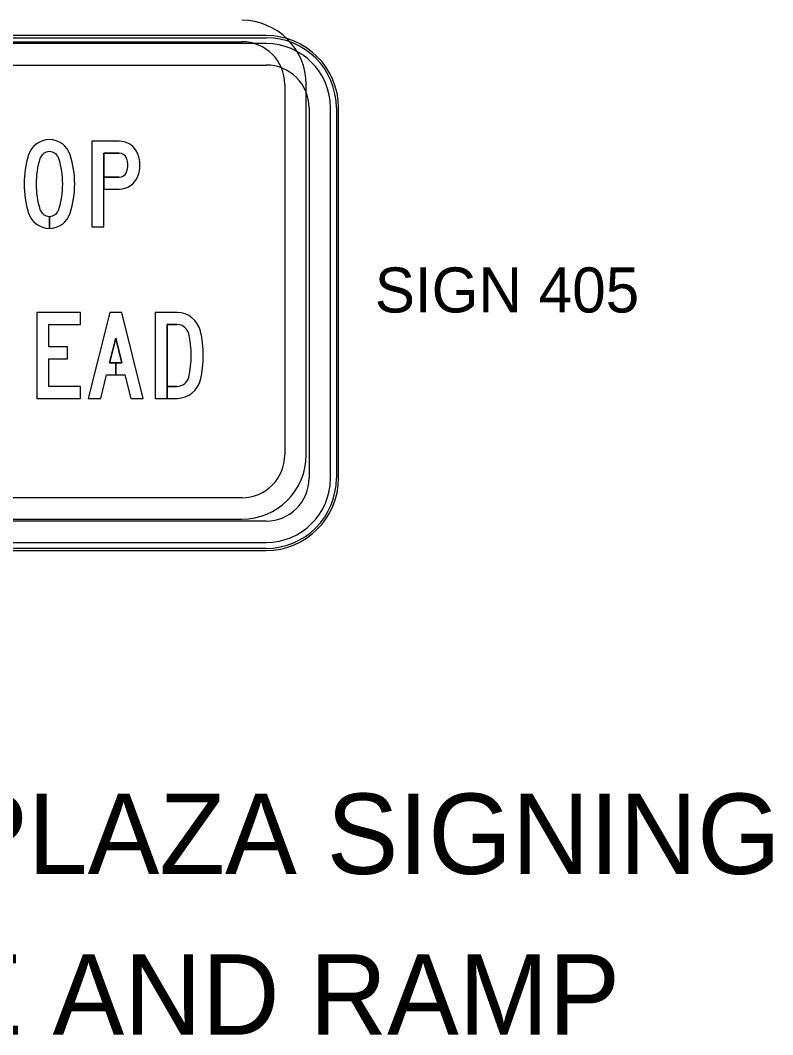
# Model space of a CAD drawing. Extents: x -63400 to -62632, y -1624834 to -1624417.
# Drawn here: x -62883.8 to -62837, y -1624821.5 to -1624758.4 of the extents above; entities that cross this region are included whole.
import ezdxf

# ---------------------------------------------------------------- set-up
doc = ezdxf.new("R2010")
doc.units = 0
for name, color, linetype in [('GSColorFill', 7, 'Continuous'), ('SignPanel', 7, 'Continuous'), ('TextLabel', 7, 'Continuous'), ('TextMisc', 7, 'Continuous')]:
    doc.layers.add(name, color=color, linetype=linetype)

msp = doc.modelspace()

# ---------------------------------------------------------------- linework, layer by layer
at = {"layer": 'GSColorFill'}
for p, q in [((-62868.5, -1624759.357), (-62923.531, -1624759.357)), ((-62868.5, -1624759.357), (-62923.531, -1624759.357)), ((-62923.531, -1624759.49), (-62868.5, -1624759.49)), ((-62868.5, -1624759.857), (-62923.531, -1624759.857)), ((-62923.531, -1624761.19), (-62868.5, -1624761.19)), ((-62865.833, -1624763.857), (-62865.833, -1624786.889)), ((-62864.5, -1624786.889), (-62864.5, -1624763.857)), ((-62864.133, -1624763.857), (-62864.133, -1624786.889)), ((-62864, -1624786.889), (-62864, -1624763.857)), ((-62864, -1624786.889), (-62864, -1624763.857)), ((-62868.5, -1624789.556), (-62923.518, -1624789.556)), ((-62923.531, -1624791.389), (-62868.5, -1624791.389)), ((-62868.5, -1624791.256), (-62923.53, -1624791.256)), ((-62923.53, -1624791.389), (-62868.5, -1624791.389)), ((-62923.518, -1624790.889), (-62868.5, -1624790.889))]:
    msp.add_line(p, q, dxfattribs=at)
for centre, radius, start, end in [((-62868.5, -1624763.857), 4.5, 0, 90), ((-62868.5, -1624763.857), 4.5, 0, 90), ((-62868.5, -1624763.857), 4.367, 0, 90), ((-62868.5, -1624763.857), 4, 0, 90), ((-62868.5, -1624763.857), 2.667, 0, 90), ((-62868.5, -1624786.889), 4, 270, 0), ((-62868.5, -1624786.889), 2.667, 270, 0), ((-62868.5, -1624786.889), 4.5, 270, 0), ((-62868.5, -1624786.889), 4.367, 270, 0), ((-62868.5, -1624786.889), 4.5, 270, 0)]:
    msp.add_arc(centre, radius, start, end, dxfattribs=at)
at = {"layer": 'SignPanel'}
for p, q in [((-62925.04, -1624759.741), (-62870.008, -1624759.741)), ((-62867.341, -1624762.407), (-62867.341, -1624785.439)), ((-62866.008, -1624785.439), (-62866.008, -1624762.407)), ((-62877.649, -1624765.923), (-62879.337, -1624765.923)), ((-62881.977, -1624770.603), (-62881.977, -1624771.35)), ((-62881.977, -1624771.35), (-62881.977, -1624770.603)), ((-62881.977, -1624770.603), (-62881.977, -1624771.35)), ((-62881.977, -1624771.35), (-62881.977, -1624770.603)), ((-62874.652, -1624781.177), (-62874.04, -1624781.177)), ((-62874.04, -1624781.177), (-62874.652, -1624781.177)), ((-62874.04, -1624781.177), (-62874.652, -1624781.177)), ((-62874.04, -1624781.923), (-62874.04, -1624781.923)), ((-62870.008, -1624788.106), (-62925.027, -1624788.106)), ((-62925.027, -1624789.439), (-62870.008, -1624789.439))]:
    msp.add_line(p, q, dxfattribs=at)
for points in [[(-62879.337, -1624765.923), (-62879.337, -1624771.257), (-62878.591, -1624771.257), (-62878.591, -1624768.91), (-62877.649, -1624768.91)], [(-62877.649, -1624765.923), (-62879.337, -1624765.923), (-62879.337, -1624771.257), (-62878.591, -1624771.257), (-62878.591, -1624766.67), (-62877.649, -1624766.67)], [(-62877.649, -1624765.923), (-62879.337, -1624765.923), (-62879.337, -1624771.257), (-62878.591, -1624771.257), (-62878.591, -1624766.67), (-62877.649, -1624766.67)], [(-62877.649, -1624766.67), (-62878.591, -1624766.67), (-62878.591, -1624768.163), (-62877.649, -1624768.163)], [(-62877.649, -1624768.163), (-62878.59, -1624768.163), (-62878.59, -1624768.91), (-62877.649, -1624768.91)], [(-62877.649, -1624768.163), (-62878.59, -1624768.163), (-62878.59, -1624768.91), (-62877.649, -1624768.91)], [(-62874.04, -1624776.59), (-62875.399, -1624776.59), (-62875.399, -1624781.923), (-62874.04, -1624781.923)], [(-62874.04, -1624776.59), (-62875.399, -1624776.59), (-62875.399, -1624781.923), (-62874.652, -1624781.923), (-62874.652, -1624777.337), (-62874.04, -1624777.337)], [(-62874.04, -1624776.59), (-62875.399, -1624776.59), (-62875.399, -1624781.923), (-62874.652, -1624781.923), (-62874.652, -1624777.337), (-62874.04, -1624777.337)], [(-62874.04, -1624777.337), (-62874.652, -1624777.337), (-62874.652, -1624781.177)], [(-62874.652, -1624781.177), (-62874.652, -1624781.923), (-62874.04, -1624781.923)], [(-62874.652, -1624781.177), (-62874.652, -1624781.923), (-62874.04, -1624781.923)]]:
    msp.add_lwpolyline(points, dxfattribs=at)
for points in [[(-62882.012, -1624781.177), (-62882.012, -1624779.47), (-62880.844, -1624779.47), (-62880.844, -1624778.723), (-62882.012, -1624778.723), (-62882.012, -1624777.337), (-62880.039, -1624777.337), (-62880.039, -1624776.59), (-62882.759, -1624776.59), (-62882.759, -1624781.923), (-62880.039, -1624781.923), (-62880.039, -1624781.177)], [(-62882.012, -1624781.177), (-62882.012, -1624779.47), (-62880.844, -1624779.47), (-62880.844, -1624778.723), (-62882.012, -1624778.723), (-62882.012, -1624777.337), (-62880.039, -1624777.337), (-62880.039, -1624776.59), (-62882.759, -1624776.59), (-62882.759, -1624781.923), (-62880.039, -1624781.923), (-62880.039, -1624781.177)], [(-62882.012, -1624781.177), (-62882.012, -1624779.47), (-62880.844, -1624779.47), (-62880.844, -1624778.723), (-62882.012, -1624778.723), (-62882.012, -1624777.337), (-62880.039, -1624777.337), (-62880.039, -1624776.59), (-62882.759, -1624776.59), (-62882.759, -1624781.923), (-62880.039, -1624781.923), (-62880.039, -1624781.177)], [(-62878.422, -1624780.457), (-62877.282, -1624780.457), (-62876.915, -1624781.923), (-62876.145, -1624781.923), (-62877.479, -1624776.59), (-62878.225, -1624776.59), (-62879.559, -1624781.923), (-62878.789, -1624781.923)], [(-62877.852, -1624779.71), (-62878.236, -1624779.71), (-62877.852, -1624778.175), (-62877.468, -1624779.71), (-62877.852, -1624779.71), (-62877.852, -1624780.457), (-62877.282, -1624780.457), (-62876.915, -1624781.923), (-62876.145, -1624781.923), (-62877.479, -1624776.59), (-62878.225, -1624776.59), (-62879.559, -1624781.923), (-62878.789, -1624781.923), (-62878.422, -1624780.457), (-62877.852, -1624780.457)], [(-62877.852, -1624779.71), (-62878.236, -1624779.71), (-62877.852, -1624778.175), (-62877.468, -1624779.71), (-62877.852, -1624779.71), (-62877.852, -1624780.457), (-62877.282, -1624780.457), (-62876.915, -1624781.923), (-62876.145, -1624781.923), (-62877.479, -1624776.59), (-62878.225, -1624776.59), (-62879.559, -1624781.923), (-62878.789, -1624781.923), (-62878.422, -1624780.457), (-62877.852, -1624780.457)], [(-62877.468, -1624779.71), (-62877.852, -1624778.175), (-62878.236, -1624779.71)]]:
    msp.add_lwpolyline(points, close=True, dxfattribs=at)
for centre, radius, start, end in [((-62870.008, -1624762.407), 4, 360, 90), ((-62870.008, -1624762.407), 2.667, 360, 90), ((-62877.649, -1624767.177), 1.253, 21.1002, 90), ((-62877.649, -1624767.177), 1.253, 21.1002, 90), ((-62877.649, -1624767.177), 1.253, 21.1002, 90), ((-62877.649, -1624767.177), 0.507, 21.1002, 90), ((-62877.649, -1624767.177), 0.507, 21.1002, 90), ((-62877.649, -1624767.177), 0.507, 21.1002, 90), ((-62878.271, -1624767.417), 1.92, 338.8998, 21.10019), ((-62878.271, -1624767.417), 1.92, 338.8998, 21.10019), ((-62878.271, -1624767.417), 1.92, 338.8998, 21.10019), ((-62878.271, -1624767.417), 1.173, 338.8998, 21.10019), ((-62878.271, -1624767.417), 1.173, 338.89981, 21.1002), ((-62878.271, -1624767.417), 1.173, 338.89981, 21.1002), ((-62877.649, -1624767.657), 0.507, 270, 338.8998), ((-62877.649, -1624767.657), 0.507, 270, 338.8998), ((-62877.649, -1624767.657), 0.507, 270, 338.8998), ((-62877.649, -1624767.657), 1.253, 270, 338.8998), ((-62877.649, -1624767.657), 1.253, 270, 338.8998), ((-62877.649, -1624767.657), 1.253, 270, 338.8998), ((-62870.008, -1624785.439), 4, 270, 0), ((-62870.008, -1624785.439), 2.667, 270, 360)]:
    msp.add_arc(centre, radius, start, end, dxfattribs=at)
for centre, major_axis, ratio, start_param, end_param in [((-62881.977, -1624767.19), (0, 1.36), 0.999994, 5.014824, 7.551546), ((-62881.977, -1624767.19), (0, 1.36), 0.999994, 5.014824, 7.551546), ((-62881.977, -1624767.19), (0, 1.36), 0.999994, 5.014824, 7.551546), ((-62877.49, -1624768.59), (0, 6.06), 0.999994, 1.268361, 1.873232), ((-62877.49, -1624768.59), (0, 6.06), 0.999994, 1.268361, 1.873232), ((-62877.49, -1624768.59), (0, 6.06), 0.999994, 1.268361, 1.873232), ((-62881.977, -1624767.19), (0, 0.613), 0.999994, 5.014824, 7.551546), ((-62881.977, -1624767.19), (0, 0.613), 0.999994, 5.014824, 7.551546), ((-62881.977, -1624767.19), (0, 0.613), 0.999994, 5.014824, 7.551546), ((-62886.464, -1624768.59), (0, 6.06), 0.999994, 4.409954, 5.014824), ((-62886.464, -1624768.59), (0, 6.06), 0.999994, 4.409954, 5.014824), ((-62886.464, -1624768.59), (0, 6.06), 0.999994, 4.409954, 5.014824), ((-62877.49, -1624768.59), (0, 5.314), 0.999994, 1.268361, 1.873232), ((-62877.49, -1624768.59), (0, 5.314), 0.999994, 1.268361, 1.873232), ((-62877.49, -1624768.59), (0, 5.314), 0.999994, 1.268361, 1.873232), ((-62886.464, -1624768.59), (0, 5.314), 0.999994, 4.409954, 5.014824), ((-62886.464, -1624768.59), (0, 5.314), 0.999994, 4.409954, 5.014824), ((-62886.464, -1624768.59), (0, 5.314), 0.999994, 4.409954, 5.014824), ((-62881.977, -1624769.99), (0, 1.36), 0.999994, 1.873232, 4.409954), ((-62881.977, -1624769.99), (0, 1.36), 0.999994, 1.873232, 3.141593), ((-62881.977, -1624769.99), (0, 1.36), 0.999994, 1.873232, 3.141593), ((-62881.977, -1624769.99), (0, 0.613), 0.999994, 1.873232, 4.409954), ((-62881.977, -1624769.99), (0, 0.613), 0.999994, 1.873232, 3.141593), ((-62881.977, -1624769.99), (0, 0.613), 0.999994, 1.873232, 3.141593), ((-62881.977, -1624769.99), (0, 0.613), 0.999994, 3.142027, 4.409954), ((-62881.977, -1624769.99), (0, 0.613), 0.999994, 3.142027, 4.409954), ((-62881.977, -1624769.99), (0, 1.36), 0.999994, 3.141789, 4.409954), ((-62881.977, -1624769.99), (0, 1.36), 0.999994, 3.141789, 4.409954), ((-62874.04, -1624778.083), (0, 1.493), 0.999992, 4.941184, 6.283185), ((-62874.04, -1624778.083), (0, 1.493), 0.999992, 4.941184, 6.283185), ((-62874.04, -1624778.083), (0, 1.493), 0.999992, 4.941184, 6.283185), ((-62874.04, -1624778.083), (0, 0.747), 0.999992, 4.941184, 6.283185), ((-62874.04, -1624778.083), (0, 0.747), 0.999992, 4.941184, 6.283185), ((-62874.04, -1624778.083), (0, 0.747), 0.999992, 4.941184, 6.283185), ((-62879.079, -1624779.257), (0, 5.92), 0.999992, 4.483594, 4.941184), ((-62879.079, -1624779.257), (0, 5.92), 0.999992, 4.483594, 4.941184), ((-62879.079, -1624779.257), (0, 5.92), 0.999992, 4.483594, 4.941184), ((-62879.079, -1624779.257), (0, 6.667), 0.999992, 4.483594, 4.941184), ((-62879.079, -1624779.257), (0, 6.667), 0.999992, 4.483594, 4.941184), ((-62879.079, -1624779.257), (0, 6.667), 0.999992, 4.483594, 4.941184), ((-62874.04, -1624780.43), (0, 0.747), 0.999992, 3.141593, 4.483594), ((-62874.04, -1624780.43), (0, 0.747), 0.999992, 3.141593, 4.483594), ((-62874.04, -1624780.43), (0, 0.747), 0.999992, 3.141593, 4.483594), ((-62874.04, -1624780.43), (0, 1.493), 0.999992, 3.141593, 4.483594), ((-62874.04, -1624780.43), (0, 1.493), 0.999992, 3.141593, 4.483594), ((-62874.04, -1624780.43), (0, 1.493), 0.999992, 3.141593, 4.483594)]:
    msp.add_ellipse(centre, major_axis=major_axis, ratio=ratio, start_param=start_param, end_param=end_param, dxfattribs=at)

# ---------------------------------------------------------------- texts
at = {"layer": 'TextLabel'}
msp.add_text('SIGN 405', height=2.8, dxfattribs=at).set_placement((-62861.746, -1624776.582))
at = {"layer": 'TextMisc'}
for s, p in [(' INTERIOR PLAZA SIGNING ', (-62923.437, -1624811.508)), ('   MAINLINE AND RAMP    ', (-62920.792, -1624821.508))]:
    msp.add_text(s, height=5, rotation=360, dxfattribs=at).set_placement(p)

doc.saveas('drawing.dxf')
